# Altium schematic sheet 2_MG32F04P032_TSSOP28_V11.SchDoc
size 330 x 228 mm; PageSetup: Record=PageOptions|CenterHorizontal=True|CenterVertical=True|PrintScale=0.86|XCorrection=1.00|YCorrection=1.00|PrintKind=0|BorderSize=5000000|LeftOffset=0|BottomOffset=0|Orientation=2|PaperLength=1000|PaperWidth=1000|Scale=100|PaperSource=7|PrintQuality=-4|MediaType=1|DitherType=10|PaperKind=A4 (210 x 297 mm)|PrintScaleMode=1
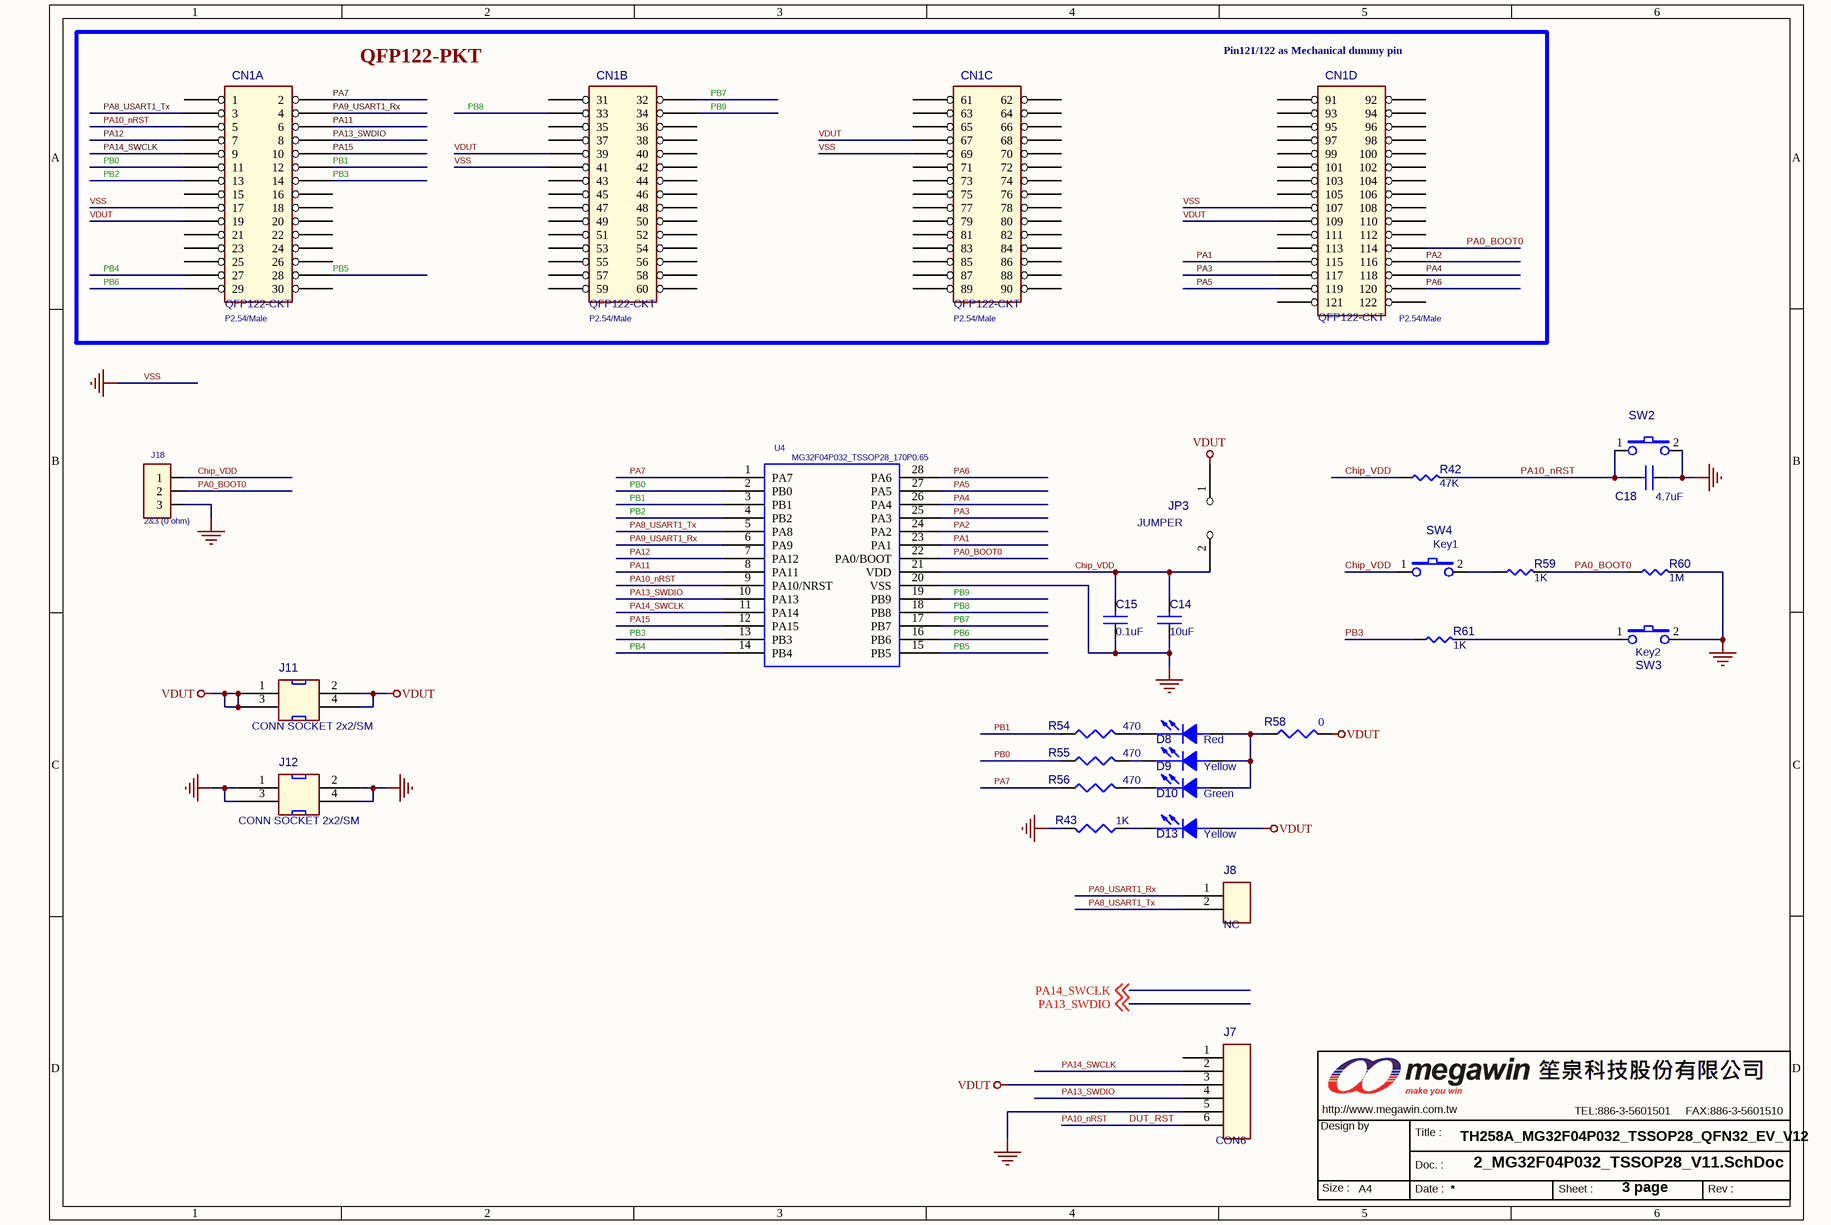
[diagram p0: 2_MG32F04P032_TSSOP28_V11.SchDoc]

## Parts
C14  10uF  [C-0603]
C15  0.1uF  [C-0603]
C18  4.7uF  [C-0603]
CN1  QFP122-CKT  Package: P2.54/Male  [QFP122-P2.54-CKT]  (parts A,B,C,D of 4)
D8  Red  [0805D]
D9  Yellow  [0805D]
D10  Green  [0805D]
D13  Yellow  [0805D]
J7  CON6  [PS6P254]
J8  NC  [PS2P254]
J11  CONN SOCKET 2x2/SM  [PS2X2P254]
J12  CONN SOCKET 2x2/SM  [PS2X2P254]
J18  2&3 (0 ohm)  [PS3P254]
JP3  JUMPER  [PS2P254]
MW1  OrgAddr3: TEL:886-3-5601501     FAX:886-3-5601510  [MEGAWIN_3.4]  (hidden comment: MW-A4)  (graphical)
R42  47K  [R-0603]
R43  1K  [R-0603]
R54  470  [R-0603]
R55  470  [R-0603]
R56  470  [R-0603]
R58  0  [R-0603]
R59  1K  [R-0603]
R60  1M  [R-0603]
R61  1K  [R-0603]
SW2  SW TACT-SPST  [SW_T_2P]  (value not drawn)
SW3  Key2  [SW_T_2P]
SW4  Key1  [SW_T_2P]
U4  MG32F04P032_TSSOP28_170P0.65  [TSSOP28_170P065]

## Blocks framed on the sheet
QFP122-PKT: CN1

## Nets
VDUT: CN1.19 CN1.39 CN1.67 CN1.109 D13.1(ANODE) J7.3 J11.1 J11.2 J11.3 J11.4 JP3.1 R58.2
VSS: C14.1 C15.1 C18.1 CN1.17 CN1.41 CN1.69 CN1.107 J7.5 J12.1 J12.2 J12.3 J12.4 J18.3 R43.1 R60.2 SW2.2 SW3.2 U4.20(VSS)  [also labelled GND_POWER]
Chip_VDD: C14.2 C15.2 J18.1 JP3.2 R42.1 SW4.1 U4.21(VDD)
DUT_RST: C18.2 CN1.5 J7.6 R42.2 SW2.1 U4.9(PA10/NRST)  [also labelled PA10_nRST]
PA0_BOOT0: CN1.114 J18.2 R59.2 R60.1 U4.22(PA0/BOOT)
PA1: CN1.115 U4.23(PA1)
PA2: CN1.116 U4.24(PA2)
PA3: CN1.117 U4.25(PA3)
PA4: CN1.118 U4.26(PA4)
PA5: CN1.119 U4.27(PA5)
PA6: CN1.120 U4.28(PA6)
PA7: CN1.2 R56.1 U4.1(PA7)
PA8_USART1_Tx: CN1.3 J8.2 U4.5(PA8)
PA9_USART1_Rx: CN1.4 J8.1 U4.6(PA9)
PA11: CN1.6 U4.8(PA11)
PA12: CN1.7 U4.7(PA12)
PA13_SWDIO: CN1.8 J7.4 U4.10(PA13) ; off-sheet PA13_SWDIO
PA14_SWCLK: CN1.9 J7.2 U4.11(PA14) ; off-sheet PA14_SWCLK
PA15: CN1.10 U4.12(PA15)
PB0: CN1.11 R55.1 U4.2(PB0)
PB1: CN1.12 R54.1 U4.3(PB1)
PB2: CN1.13 U4.4(PB2)
PB3: CN1.14 R61.1 U4.13(PB3)
PB4: CN1.27 U4.14(PB4)
PB5: CN1.28 U4.15(PB5)
PB6: CN1.29 U4.16(PB6)
PB7: CN1.32 U4.17(PB7)
PB8: CN1.33 U4.18(PB8)
PB9: CN1.34 U4.19(PB9)
NetD8_1: D8.1(ANODE) D9.1(ANODE) D10.1(ANODE) R58.1
NetD8_2: D8.2(CATHODE) R54.2
NetD9_2: D9.2(CATHODE) R55.2
NetD10_2: D10.2(CATHODE) R56.2
NetD13_2: D13.2(CATHODE) R43.2
NetR59_1: R59.1 SW4.2
NetR61_2: R61.2 SW3.1

Not connected (* = marked no-connect by the designer): CN1 1 15 16 18 20 21 22 23 24 25 26 30 31 35 36 37 38 40 42 43 44 45 46 47 48 49 50 51 52 53 54 55 56 57 58 59 60 61 62 63 64 65 66 68 70 71 72 73 74 75 76 77 78 79 80 81 82 83 84 85 86 87 88 89 90 91 92 93 94 95 96 97 98 99 100 101 102 103 104 105 106 108 110 111 112 113 121 122; J7 1

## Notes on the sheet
- (near CN1) Pin121/122 as Mechanical dummy pin
- TH258A_MG32F04P032_TSSOP28_QFN32_EV_V12
- 3 page

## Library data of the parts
C14 C15 C18 = CAP NP_Dup1
D8-D10 D13 = LED
J7 = CON6_Dup1
J8 = CON2
J18 = CON3
MW1 = MW_A4_2
R42 R59-R61 = R_Dup3
R43 R54-R56 R58 = R_Dup4
SW3 SW4 = SW TACT-SPST
U4 = MDF101A/TSSOP28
